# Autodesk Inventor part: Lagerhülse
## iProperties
Shininess: 20.0
Angle Display Precision: 2
Document Length Units: 11269
Document Angle Units: 11279
Document Time Units: 11290
Document Mass Units: 11283
Document Length Units Precision: 3
Document Angle Units Precision: 2
Created: 2003-02
Part Number: Lagerhülse
Material: S275JR
Document SubType Name: Modellieren
Designer: Administrator
Density: 0.0
Volumn: 0.0
Area: 0.0
PropertySet Name: Model Information
Control State: 0
Master: False
Checked Out: False
Author: Administrator
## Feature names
1. Grundkörper [Revolution]
2. Passfedernut [Extrusion]
3. Fliehgewichtnut [Extrusion]
4. Zugfedernut [Extrusion]
5. Bohrungen1 für Kerbstifte [Hole]
6. Bohrungen2 für Kerbstifte [Mirror]
7. Wellennut [Extrusion]
8. Fase1 [Chamfer]
